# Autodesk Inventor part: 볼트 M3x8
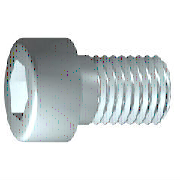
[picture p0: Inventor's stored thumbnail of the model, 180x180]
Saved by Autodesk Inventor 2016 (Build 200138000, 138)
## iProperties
IsCustomPart: 0
Created: 2012-02
Part Number: 볼트 M3x8
Material: 강철, 연강
Description: 6각머리 태핑 나사
Document SubType Name: Modeling
Standard: KS B 1003
Designer: mduedu
Standards Organization: KS
Language: ko-KR
Size Designation: M 3 x 8
Categories: <MemberInstance><Categories><Category DisplayName="조임쇠" InternalName="e4da775c-781d-43d5-af7c-5136215cf5a6" Mnemonic="FSTN"><Category DisplayName="볼트" InternalN
Density: 7.85 g/cm^3
Appearance: 강철
Mass: 0.928661 g
Surface Area: 1.83001 cm^2
Volume: 0.118301 cm^3
Author: mduedu
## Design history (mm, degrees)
sketch "스케치1"
  geometry: L1 (-0.867, 0)-(8, 0); L2 (8, 0)-(8, 1.5); L3 (8, 1.5)-(1.25, 1.5); L4 (1.25, 1.5)-(0.943, 1.5); L5 (0.943, 1.5)-(0, 1.5); L6 (0, 1.5)-(0, 2.75); L7 (0, 2.75)-(-3, 2.75); L8 (-3, 2.75)-(-3, 1.443); L9 (-3, 1.443)-(-1.7, 1.443); L10 (-1.7, 1.443)-(-0.867, 0); L11 (-5.2, 0)-(10.2, 0) reference; L12 (0, -0.55)-(0, 3.3) reference; L13 (1.25, 1.5)-(0, 1.5)
  constraints: 22 end point, 6 parallel, 2 collinear, 2 perpendicular, 1 horizontal, 1 point on line
  dimensions: "d1" = 6.75 distance from line of L3.end L2 (= GEL); "d2" = 0.30683 distance of L4.end L3.end (computed from GAL); "d3" = 3 distance between parallel lines of L8 L6 (= KOH); "d4" = 1.3 distance of L8.end L9.end (= INTI); "d5" = 60 deg angle of L10 L1; "d6" = 3 diameter of L3 L1 (= GD); "d7" = 3 diameter of L5 L1 (= BDM); "d8" = 2.88675 diameter of L9 L1 (= 1.1547 x SW); "d9" = 5.5 diameter of L7 L1 (= KOD); "d26" = 8 distance between parallel lines of L12 L2 (= NLG)
revolve "본체" sketch "스케치1" stored, may be unused: angle "d10" = 90 deg
sketch "스케치2"
  geometry: L1 (0, -3.85)-(0, 3.85) reference; L2 (-3.85, 0)-(3.85, 0) reference; L3 (1.443, 0)-(0.722, -1.25); L4 (0.722, -1.25)-(-0.722, -1.25); L5 (-0.722, -1.25)-(-1.443, 0); L6 (-1.443, 0)-(-0.722, 1.25); L7 (-0.722, 1.25)-(0.722, 1.25); L8 (0.722, 1.25)-(1.443, 0); 2 further points
  constraints: 12 end point, 1 coincident, 1 horizontal alignment, 1 point on line, 12 other
extrude "슬롯" join sketch "스케치2" stored distance "d11" = 10; taper "d12" = 0 deg
workplane "Work Plane1"
fillet "Fillet2" dims "d30" = 0.1 (= R)
body "Solid1"
fillet "모깎기1" dims "d17" = 0.3 (= RR)
feature "스레드" dims "d13" = 6.75 (= GEL), "d14" = 0
chamfer "모따기1" distance "d15" = 0.30673 (= -0.5 x SPD + 0.5 x GD); stored, may be unused: second distance "d16" = 0.30673 (= GUL), angle "d27" = 45 deg
other parameters: "GD" = 3 (= NND) [user parameter; used in 2 equation terms], "NLG" = 8 [user parameter; used in 1 equation term], "GEL" = 6.75 [user parameter; used in 2 equation terms], "KOD" = 5.5 [user parameter; used in 1 equation term], "KOH" = 3 [user parameter; used in 1 equation term], "INTI" = 1.3 [user parameter; used in 1 equation term], "GAL" = 0.30673 (= 0.61345 x PTC) [user parameter; used in 1 equation term], "GUL" = 0.30673 (= 0.61345 x PTC) [user parameter; used in 1 equation term], "BDM" = 3 (= NND) [user parameter; used in 1 equation term], "SW" = 2.5 [user parameter; used in 2 equation terms], "RR" = 0.3 [user parameter; used in 1 equation term], "SPD" = 2.38655 (= NND - 1.2269 x PTC) [user parameter; used in 1 equation term], "d19" = 0, "d28" = 0, "d29" = 0, "R" = 0.1 [user parameter; used in 1 equation term], "PHH" = 0.1 [user parameter], "GD1" = 2.38655 (= THREADDIA - 1.2269 x PTC) [user parameter], "THREADDIA" = 3 [user parameter; used in 1 equation term], "FAWI" = 45 deg [user parameter], "PTC" = 0.5 [user parameter; used in 5 equation terms], "NND" = 3 [user parameter; used in 3 equation terms], "TOA" = 30 deg [user parameter], "E0" = 2.8875 (= 1.155 x SW) [user parameter]
